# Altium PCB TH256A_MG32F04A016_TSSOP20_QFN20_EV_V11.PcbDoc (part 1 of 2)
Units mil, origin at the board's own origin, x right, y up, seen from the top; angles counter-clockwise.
Board outline 4094.49 x 2637.8 mil, 2 copper layers (Top Layer, Bottom Layer); 134 components, 99 nets, 551 pads, 259 vias.
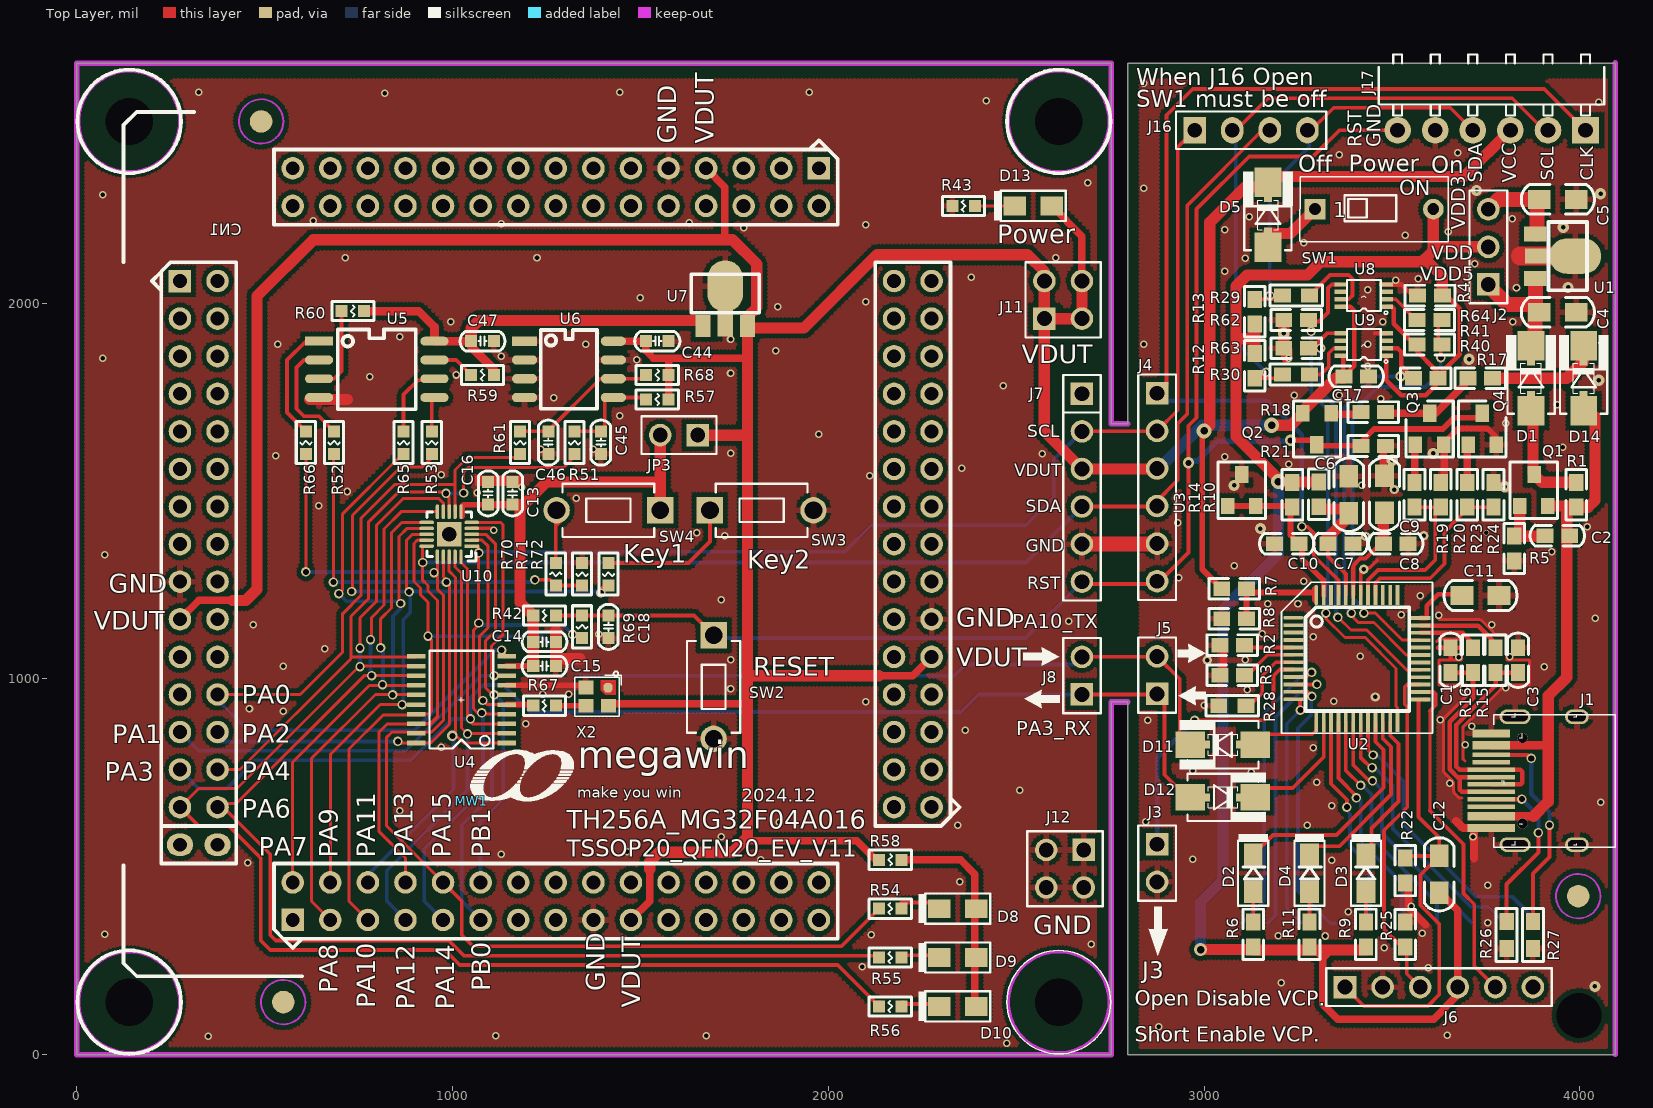
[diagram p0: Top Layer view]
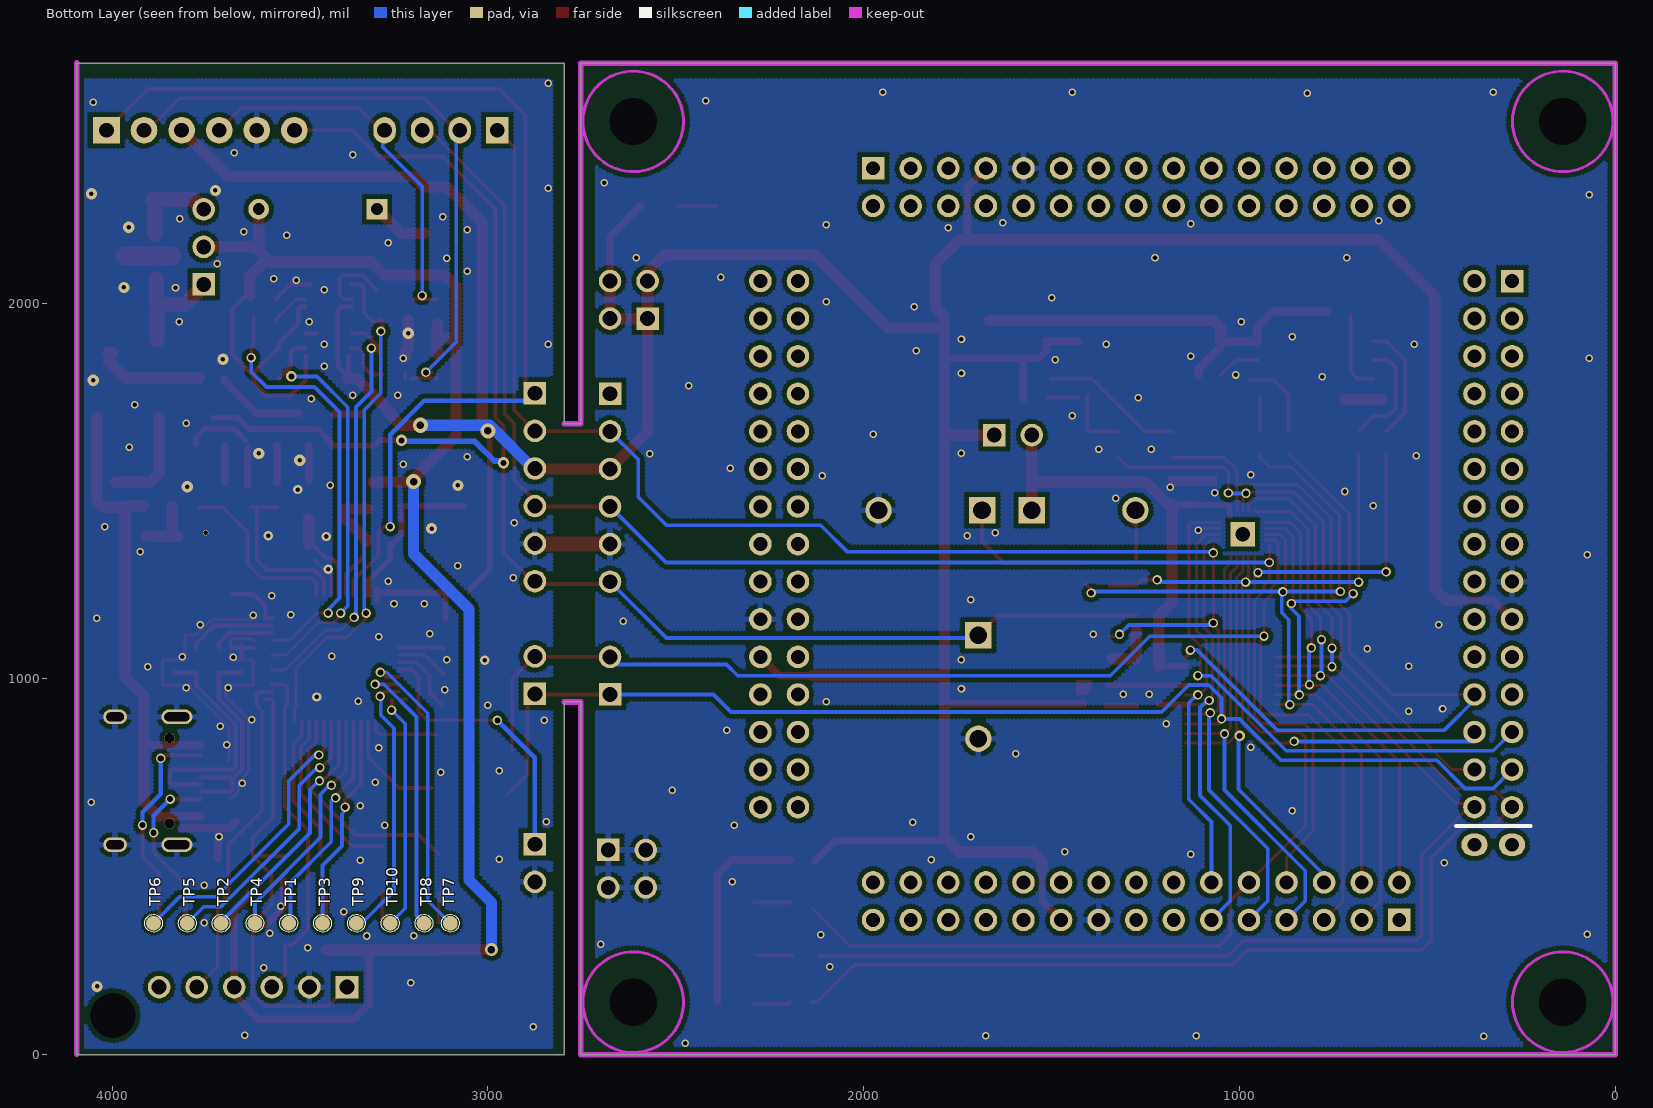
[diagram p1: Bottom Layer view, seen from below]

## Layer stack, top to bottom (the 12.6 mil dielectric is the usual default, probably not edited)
Top Layer: signal copper 1.4
Dielectric: dielectric 12.6, FR-4, Dk 4.8
Bottom Layer: signal copper 1.4

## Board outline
0,0 0,2637.8 2753.39,2637.8 2753.39,1678.74 2796.69,1678.74 2796.69,2637.8 4094.49,2637.8 4094.49,0 2796.69,0 2796.69,938.74 2753.39,938.74 2753.39,0

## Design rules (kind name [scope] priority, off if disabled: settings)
Clearance 12 [All] p1 off: gap=12
Clearance 7 [All] p2 off: gap=7
Clearance 6 [All] p3: gap=6
HoleSize 500-HoleSize [All] p1: absolutevalues=TRUE maxlimit=1500 minlimit=1 maxpercent=80.000 minpercent=20.000
PolygonConnect VIA [ISVIA] p1: connectstyle=Direct reliefconductorwidth=10 reliefentries=4 polygonreliefangle="90 Angle"
PolygonConnect "15 PolygonConnect" [All] p2: connectstyle=Relief reliefconductorwidth=15 reliefentries=4 polygonreliefangle="90 Angle"
RoomDefinition "3_MG32F04A016_QFN20 " [InComponentClass('3_MG32F04A016_QFN20 ')] p1: confinementstyle=ConfineIn formatcopy=TRUE lockcomponents=FALSE outline -70.96,-260.26 4008.04,-260.26 4008.04,2917.74 -70.96,2917.74
RoomDefinition 2_MG32F04A016_TSSOP20 [InComponentClass('2_MG32F04A016_TSSOP20')] p2: confinementstyle=ConfineIn formatcopy=TRUE lockcomponents=FALSE outline -190,-175 4240.04,-175 4240.04,2710 -190,2710
RoomDefinition 1_MLink_V14 [InComponentClass('1_MLink_V14')] p3: confinementstyle=ConfineIn formatcopy=TRUE lockcomponents=FALSE outline -110,-220 4180,-220 4180,2775 -110,2775
RoutingVias [All] p1: holewidth=16 width=25 viastyle="Through Hole" minholewidth=12 minwidth=25 maxholewidth=28 maxwidth=50
ShortCircuit [All] p1 off: allowed=FALSE
SilkscreenOverComponentPads [All] p1: minsilkscreentomaskgap=10
SolderMaskExpansion [All] p1: expansion=4
UnRoutedNet [All] p1 off:
Width [All] p1: maxlimit=100 minlimit=6 preferedwidth=8
24 further rules are at their usual default settings.

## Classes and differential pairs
component class 1_MLink_V14: C1 C2 C3 C4 C5 C6 C7 C8 C9 C10 C11 C12 C17 D1 D2 D3 D4 D5 D11 D12 D14 J1 J2 J3 J4 J5 J6 J16 J17 MW1 Q1 Q2 Q3 Q4 R1 R2 R3 R4 R5 R6 R7 R8 R9 R10 R11 R12 R13 R14 R15 R16 R17 R18 R19 R20 R21 R22 R23 R24 R25 R26 R27 R28 R29 R30 R40 R41 R62 R63 R64 SW1 TP1 TP2 TP3 TP4 TP5 TP6 TP7 TP8 TP9 TP10 U1 U2 U3 U8 U9
component class 2_MG32F04A016_TSSOP20: C14 C15 C18 C44 C45 C46 C47 CN1 D8 D9 D10 D13 J7 J8 J11 J12 JP3 R42 R43 R51 R52 R53 R54 R55 R56 R57 R58 R59 R60 R61 R65 R66 R67 R68 R69 R70 R71 R72 SW2 SW3 SW4 U4 U5 U6 U7 X2
component class "3_MG32F04A016_QFN20 ": C13 C16 U10

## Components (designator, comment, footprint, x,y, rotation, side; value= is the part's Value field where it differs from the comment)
C1 "15pF" 0603C 3655.59,1050 r270 top
C2 "0.1uF" 0603C 3940,1381.26 r0 top
C3 "15pF" 0603C 3835.59,1050 r270 top
C4 "4.7uF" 0805C 3941.38,1975.94 r0 top
C5 "4.7uF" 0805C 3941.38,2275.94 r0 top
C6 "4.7uF" 0805C 3385,1490 r90 top
C7 "0.1uF" 0603C 3363,1360 r0 top
C8 "0.1uF" 0603C 3510,1360 r0 top
C9 "4.7uF" 0805C 3480,1491.26 r90 top
C10 "0.1uF" 0603C 3220,1360 r0 top
C11 "4.7uF" 0805C 3735.59,1221.9 r0 top
C12 "4.7uF" 0805C 3625.59,480 r90 top
C13 "10uF" C-0603 1160.04,1493.74 r90 top
C14 "10uF" C-0603 1245.04,1098.74 r0 top
C15 "0.1uF" C-0603 1245.04,1034.34 r0 top
C16 "0.1uF" C-0603 1095.04,1493.74 r90 top
C17 "0.1uF" 0603C 3405,1805 r180 top
C18 "NC" C-0603 1415.04,1138.74 r90 top
C44 "0.1uF" C-0603 1545.04,1898.74 r0 top
C45 "47pF" C-0603 1395.04,1628.74 r270 top
C46 "47pF" C-0603 1255.04,1628.74 r270 top
C47 "0.1uF" C-0603 1080.04,1898.74 r0 top
CN1 "QFP122-CKT" QFP122-P2.54-CKT 1275.04,1358.74 r0 top locked
D1 "1N5817" DIODE_SMA_SOD323 3870,1800 r90 top
D2 "Yellow" 0805D 3130.59,483.26 r90 top
D3 "Green" 0805D 3430.59,483.26 r90 top
D4 "Red" 0805D 3280.59,483.26 r90 top
D5 "1N5817" DIODE_SMA_SOD323 3170,2235 r90 top
D8 "Red" 0805D 2344.25,388.74 r180 top
D9 "Yellow" 0805D 2344.25,258.74 r180 top
D10 "Green" 0805D 2344.25,128.74 r180 top
D11 "1N5817" DIODE_SMA_SOD323 3050.04,825 r180 top
D12 "1N5817" DIODE_SMA_SOD323 3050.04,685 r0 top
D13 "Yellow" 0805D 2545.04,2258.74 r180 top
D14 "1N5817" DIODE_SMA_SOD323 4010,1800 r90 top
J1 "CJ-USB3-C16P" USB_CF_16_SMD 3799.28,729.12 r90 top
J2 "2&3 (0 ohm)" PS3P254 3756.42,2049.69 r90 top
J3 "VCP Option" PS2P254 2875.04,560 r270 top
J4 "OnBoard ICP/SWD Connector" PS6P254 2875.04,1760 r270 top
J5 "NC" PS2P254 2875.04,960 r90 top
J6 "CON6" PS6P254 3375.04,180 r0 top
J7 "CON6" PS6P254 2675.04,1758.74 r270 top locked
J8 "NC" PS2P254 2675.04,958.74 r90 top
J11 "CONN SOCKET 2x2/SM" PS2X2P254 2575.04,1958.74 r0 top
J12 "CONN SOCKET 2x2/SM" PS2X2P254 2680,545 r180 top
J16 "When J16 Open, SW1 must be off." PS4P254 2975.04,2460 r0 top
J17 "Off Board ICP/SWD Connector" PS6P254_90 4015.04,2460 r180 top
JP3 "JUMPER" PS2P254 1652.83,1648.74 r180 top
MW1 "MW-A4" MEGAWIN_3.4_1 1051.14,674.84 r0 top
Q1 "IRLML6402" SOT23 3877.54,1501.97 r0 top
Q2 "2N3906" SOT23 3300.5,1665 r180 top
Q3 "3904" SOT23_132 3600.04,1665 r0 top
Q4 "3904" SOT23_132 3740.04,1665 r0 top
R1 "NC" 0603R#1 3990.04,1490 r270 top
R2 "NC" 0603R#1 3075.04,1090 r0 top
R3 "NC" 0603R#1 3075.04,1010 r0 top
R4 "3.3K" 0603R#1 3601,2020 r0 top
R5 "1M" 0603R#1 3825.04,1347 r270 top
R6 "1K" 0603R#1 3130.59,320.26 r270 top
R7 "30K" 0603R#1 3080,1240 r180 top
R8 "10K" 0603R#1 3080,1160 r0 top
R9 "1K" 0603R#1 3430.59,320.26 r270 top
R10 "10" 0603R#1 3305,1491.26 r90 top
R11 "1K" 0603R#1 3280.59,320.26 r270 top
R12 "1.5K" 0603R#1 3135,1833 r90 top
R13 "1.5K" 0603R#1 3135,1977 r270 top
R14 "1K" 0603R#1 3235,1490 r270 top
R15 "30" 0603R#1 3775.59,1050 r90 top
R16 "30" 0603R#1 3715.59,1050 r90 top
R17 "4.7K" 0603R#1 3735,1800 r0 top
R18 "1K" 0603R#1 3450.04,1710 r0 top
R19 "4.7K" 0603R#1 3560.04,1490 r270 top
R20 "10K" 0603R#1 3630.04,1490 r270 top
R21 "1M" 0603R#1 3450.04,1620 r180 top
R22 "47K" 0603R#1 3535.59,490 r270 top
R23 "4.7K" 0603R#1 3700.04,1490 r270 top
R24 "10K" 0603R#1 3770.04,1490 r270 top
R25 "47K" 0603R#1 3535.59,320 r270 top
R26 "5.1K" 0603R#2 3805.04,318.74 r270 top
R27 "5.1K" 0603R#2 3875.04,318.74 r90 top
R28 "0" 0603R#2 3075.04,928.74 r180 top
R29 "100" 0603R#2 3245,2020 r0 top
R30 "100" 0603R#2 3245,1810 r0 top
R40 "NC" 0603R#1 3590,1800 r180 top
R41 "1.5K" 0603R#1 3600,1890 r0 top
R42 "47K" R-0603 1245.04,1168.74 r0 top
R43 "1K" R-0603 2360.04,2258.74 r0 top
R51 "NC" R-0603 1325.04,1628.74 r90 top
R52 "NC" R-0603 685.04,1628.74 r90 top
R53 "NC" R-0603 945.04,1628.74 r90 top
R54 "470" R-0603 2165.04,388.74 r0 top
R55 "470" R-0603 2165.04,258.74 r0 top
R56 "470" R-0603 2165.04,128.74 r0 top
R57 "10K" R-0603 1545.04,1743.74 r180 top
R58 "0" R-0603 2165.04,518.74 r180 top
R59 "10K" R-0603 1080.04,1808.74 r0 top
R60 "10K" R-0603 735.04,1978.74 r180 top
R61 "NC" R-0603 1180.04,1628.74 r90 top
R62 "47k" 0603R#3 3245,1955 r0 top
R63 "47k" 0603R#3 3245,1880 r0 top
R64 "100" 0603R#3 3600,1955 r180 top
R65 "NC" R-0603 870.04,1628.74 r90 top
R66 "NC" R-0603 610.04,1628.74 r90 top
R67 "NC" R-0603 1245.04,928.74 r0 top
R68 "10K" R-0603 1545.04,1808.74 r180 top
R69 "NC" R-0603 1345.04,1138.74 r90 top
R70 "1K" R-0603 1275.04,1278.74 r270 top
R71 "1M" R-0603 1345.04,1278.74 r90 top
R72 "1K" R-0603 1415.04,1278.74 r90 top
SW1 "SW KEY-SPST" DIP2_SW 3295.04,2250 r0 top
SW2 "SW TACT-SPST" SW_T_2P 1695.04,978.74 r270 top
SW3 "Key2" SW_T_2P 1822.83,1448.74 r0 top
SW4 "Key1" SW_T_2P 1415.04,1448.74 r180 top
TP1 "T POINT A" PIN1_1H0 3530.04,350 r90 bottom
TP2 "T POINT A" PIN1_1H0 3710.04,350 r90 bottom
TP3 "T POINT A" PIN1_1H0 3440.04,350 r180 bottom
TP4 "T POINT A" PIN1_1H0 3620.04,350 r180 bottom
TP5 "T POINT A" PIN1_1H0 3800.04,350 r180 bottom
TP6 "T POINT A" PIN1_1H0 3890.04,350 r180 bottom
TP7 "T POINT A" PIN1_1H0 3100.04,350 r180 bottom
TP8 "T POINT A" PIN1_1H0 3170.04,350 r180 bottom
TP9 "T POINT A" PIN1_1H0 3350.04,350 r180 bottom
TP10 "T POINT A" PIN1_1H0 3260.04,350 r90 bottom
U1 "AIC1734-33(SOT-89)" SOT89 3881.38,2125 r270 top
U2 "MG84FG516_LQFP48" LQFP48_7X7_050 3406.51,1054.39 r270 top
U3 "TL431A" SOT23 3100,1501.97 r0 top
U4 "MG32F04A016_TSSOP20" TSSOP20_170P065 1144.04,829.54 r90 top locked
U5 "MX25L3206E" SO8_208P127 798.58,1823.74 r270 top
U6 "24C16-SOP8" SO8_150P127 1191.93,1898.74 r0 top
U7 "AIC1734-33(SOT-89)" SOT89 1725.98,1938.74 r0 top
U8 "SN74LVC2T45 (MSOP8_90P0.5)" MSOP8_90P0.5 3425,2020 r90 top
U9 "SN74LVC2T45 (MSOP8_90P0.5)" MSOP8_90P0.5 3425,1890 r90 top
U10 "MG32F04A016_QFN20  3x3P0.4mm" QFN20_3X3P040_1 991.41,1384.96 r90 top
X2 "OT20168MJBA4SL" OSC_2.0X1.6_SMD 1385.04,952.93 r180 top

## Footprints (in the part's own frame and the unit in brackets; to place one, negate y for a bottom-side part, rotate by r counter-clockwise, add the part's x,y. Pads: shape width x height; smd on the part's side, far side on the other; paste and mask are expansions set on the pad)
0603C [mil]
  rect 45x38 smd: 1(33,0) 2(-33,0)
  silkscreen extent -72,-28 72,28
0603R#1 [mil]
  rect 45x38 smd: 1(33,0) 2(-33,0)
  silkscreen extent -67,-28 67,28
0603R#2 [mil]
  rect 45x38 smd: 1(-36,0) 2(36,0)
  silkscreen extent -70,-28 70,28
0603R#3 [mil]
  rect 45x38 smd: 1(-33,0) 2(33,0)
  silkscreen extent -67,-28 67,28
0805C [mil]
  rect 60x50 smd: 1(-49.21,0) 2(49.21,0)
  silkscreen extent -97,-39 97,39
0805D [mil]
  rect 60x50 smd: 1(-49.21,0) 2(49.21,0)
  silkscreen extent -87,-40 104,40
C-0603 [mil]
  rect 32x32 smd: 1(-30,0) 2(30,0)
  silkscreen extent -60,-26 60,26
DIODE_SMA_SOD323 [mm]
  rect 2x1.8 smd: 1(-2.2,0) 2(2.2,0)
  rect 0.95x0.54 smd: 1(-1.35,0) 2(1.35,0)
  silkscreen extent -2.4,-1.68 2.92,1.68
DIP2_SW [mm]
  rect 1.4x1.4 hole 0.8: 1(0,0)
  round 1.4 hole 0.8: 2(8,0)
  silkscreen extent -1.02,-2.2 9.02,2.2
LQFP48_7X7_050 [mm]
  oval 0.254x1.35 smd: 1(-2.75,-4.292)
  rect 0.254x1.35 smd: 2(-2.25,-4.292) 3(-1.75,-4.292) 4(-1.25,-4.292) 5(-0.75,-4.292) 6(-0.25,-4.292) 7(0.25,-4.292) 8(0.75,-4.292) 9(1.25,-4.292) 10(1.75,-4.292) 11(2.25,-4.292) 12(2.75,-4.292) 25(2.763,4.292) 26(2.263,4.292) 27(1.763,4.292) 28(1.263,4.292) 29(0.763,4.292) 30(0.263,4.292) 31(-0.237,4.292) 32(-0.737,4.292) 33(-1.237,4.292) 34(-1.737,4.292) 35(-2.237,4.292) 36(-2.737,4.292)
  rect 1.35x0.254 smd: 13(4.286,-2.744) 14(4.286,-2.244) 15(4.286,-1.744) 16(4.286,-1.244) 17(4.286,-0.744) 18(4.286,-0.244) 19(4.286,0.256) 20(4.286,0.756) 21(4.286,1.256) 22(4.286,1.756) 23(4.286,2.256) 24(4.286,2.756) 37(-4.286,2.756) 38(-4.286,2.256) 39(-4.286,1.756) 40(-4.286,1.256) 41(-4.286,0.756) 42(-4.286,0.256) 43(-4.286,-0.244) 44(-4.286,-0.744) 45(-4.286,-1.244) 46(-4.286,-1.744) 47(-4.286,-2.244)
  oval 1.35x0.254 smd: 48(-4.286,-2.744)
  silkscreen extent -5.15,-5.09 5.05,5.11
MEGAWIN_3.4_1 [mil]
  silkscreen extent -2,0 272,135
MSOP8_90P0.5 [mm]
  rect 0.3x0.85 smd: 1(-0.75,-1.55) 2(-0.25,-1.55) 3(0.25,-1.55) 4(0.75,-1.55) 5(0.75,1.55) 6(0.25,1.55) 7(-0.25,1.55) 8(-0.75,1.55)
  silkscreen extent -1.26,-1.61 1.05,1.14
OSC_2.0X1.6_SMD [mil]
  oct 25x25 smd: 1(-29,-24)
  rect 40x37 smd: 2(30,-24.19) 3(30,24.19) 4(-30,24.19)
  Top Layer region: -50,-43 -50,-5 -21,-5 -9,-17 -9,-43
  silkscreen extent -64,-67 60,52
PIN1_1H0 [mm]
  round 1 smd: 1(0,0)
  silkscreen extent -0.6,-0.6 0.6,0.6
PS2P254 [mil]
  rect 60x60 hole 39.37: 1(0,0)
  round 60 hole 39.37: 2(100,0)
  silkscreen extent -50,-50 150,50
PS2X2P254 [mil]
  rect 60x60 hole 39.37: 1(0,0)
  round 60 hole 39.37: 2(0,100) 3(100,0) 4(100,100)
  silkscreen extent -50,-50 150,150
PS3P254 [mil]
  rect 60x60 hole 39.37: 1(0,0)
  round 60 hole 39.37: 2(100,0) 3(200,0)
  silkscreen extent -50,-50 250,50
PS4P254 [mil]
  rect 60x70 hole 39.37: 1(0,0)
  oval 60x70 hole 39.37: 2(100,0) 3(200,0) 4(300,0)
  silkscreen extent -50,-50 350,50
PS6P254 [mil]
  rect 60x60 hole 39.37: 1(0,0)
  round 60 hole 39.37: 2(100,0) 3(200,0) 4(300,0) 5(400,0) 6(500,0)
  silkscreen extent -50,-50 550,50
PS6P254_90 [mm]
  rect 1.8x1.8 hole 1: 1(0,0)
  round 1.8 hole 1: 2(2.54,0) 3(5.08,0) 4(7.62,0) 5(10.16,0) 6(12.7,0)
  silkscreen extent -1.27,-5.11 13.97,-1
QFN20_3X3P040_1 [mil]
  rect 64.96x64.96 hole 39.37: 0(0,0)
  rect 9x39.37 smd: 1(-31.5,-60)
  oval 9x39.37 smd: 2(-15.75,-60) 3(0,-60) 4(15.75,-60) 5(31.5,-60) 11(31.5,60) 12(15.75,60) 13(0,60) 14(-15.75,60) 15(-31.5,60)
  oval 39.37x9 smd: 6(60,-31.5) 7(60,-15.75) 8(60,0) 9(60,15.75) 10(60,31.5) 16(-60,31.5) 17(-60,15.75) 18(-60,0) 19(-60,-15.75) 20(-60,-31.5)
  silkscreen extent -71,-71 59,59
QFP122-P2.54-CKT [mil]
  rect 60x60 hole 37: 1(-700,-1000) 61(700,1000) 91(-1000,700)
  round 60 hole 37: 2(-700,-900) 3(-600,-1000) 4(-600,-900) 5(-500,-1000) 6(-500,-900) 7(-400,-1000) 8(-400,-900) 9(-300,-1000) 10(-300,-900) 11(-200,-1000) 12(-200,-900) 13(-100,-1000) 14(-100,-900) 15(0,-1000) 16(0,-900) 17(100,-1000) 18(100,-900) 19(200,-1000) 20(200,-900) 21(300,-1000) 22(300,-900) 23(400,-1000) 24(400,-900) 25(500,-1000) 26(500,-900) 27(600,-1000) 28(600,-900) 29(700,-1000) 30(700,-900) 31(1000,-700) 32(900,-700) 33(1000,-600) 34(900,-600) 35(1000,-500) 36(900,-500) 37(1000,-400) 38(900,-400) 39(1000,-300) 40(900,-300) 41(1000,-200) 42(900,-200) 43(1000,-100) 44(900,-100) 45(1000,0) 46(900,0) 47(1000,100) 48(900,100) 49(1000,200) 50(900,200) 51(1000,300) 52(900,300) 53(1000,400) 54(900,400) 55(1000,500) 56(900,500) 57(1000,600) 58(900,600) 59(1000,700) 60(900,700) 62(700,900) 63(600,1000) 64(600,900) 65(500,1000) 66(500,900) 67(400,1000) 68(400,900) 69(300,1000) 70(300,900) 71(200,1000) 72(200,900) 73(100,1000) 74(100,900) 75(0,1000) 76(0,900) 77(-100,1000) 78(-100,900) 79(-200,1000) 80(-200,900) 81(-300,1000) 82(-300,900) 83(-400,1000) 84(-400,900) 85(-500,1000) 86(-500,900) 87(-600,1000) 88(-600,900) 89(-700,1000) 90(-700,900) 92(-900,700) 93(-1000,600) 94(-900,600) 95(-1000,500) 96(-900,500) 97(-1000,400) 98(-900,400) 99(-1000,300) 100(-900,300) 101(-1000,200) 102(-900,200) 103(-1000,100) 104(-900,100) 105(-1000,0) 106(-900,0) 107(-1000,-100) 108(-900,-100) 109(-1000,-200) 110(-900,-200) 111(-1000,-300) 112(-900,-300) 113(-1000,-400) 114(-900,-400) 115(-1000,-500) 116(-900,-500) 117(-1000,-600) 118(-900,-600) 119(-1000,-700) 120(-900,-700)
  oval 70x60 hole 37: 121(-1000,-800) 122(-900,-800)
  silkscreen extent -1150,-1150 1075,1150
R-0603 [mil]
  rect 32x32 smd: 1(-30,0) 2(30,0)
  silkscreen extent -56,-26 56,26
SO8_150P127 [mil]
  rect 67x25 smd: 1(0,0)
  oval 67x25 smd: 2(0,-50) 3(0,-100) 4(0,-150) 5(236.22,-150) 6(236.22,-100) 7(236.22,-50) 8(236.22,0)
  silkscreen extent 43,-180 193,30
SO8_208P127 [mm]
  rect 0.6x1.9 smd: 1(-1.905,-3.9)
  oval 0.6x1.9 smd: 2(-0.635,-3.9) 3(0.635,-3.9) 4(1.905,-3.9) 5(1.905,3.9) 6(0.635,3.9) 7(-0.635,3.9) 8(-1.905,3.9)
  silkscreen extent -2.69,-2.63 2.69,2.63
SOT23 [mil]
  rect 36x43.31 smd: 1(-37.5,-41.97) 2(37.5,-41.97)
  rect 36x46.06 smd: 3(0.5,41.97)
  silkscreen extent -63,-74 63,75
SOT23_132 [mil]
  rect 36x43.31 smd: 1(-37.5,-41.97) 3(37.5,-41.97)
  rect 36x46.06 smd: 2(0.5,41.97)
  silkscreen extent -63,-74 63,75
SOT89 [mm]
  rect 1.016x1.5 smd: 1(-1.5,0) 3(1.5,0)
  oval 2.4x3.5 smd: 2(0,2.7)
  rect 1.016x2.6 smd: 2(0,0.6)
  silkscreen extent -2.3,0.9 2.3,3.5
SW_T_2P [mil]
  rect 70x70 hole 47.24: 1(-137.79,0)
  round 70 hole 47.24: 2(137.8,0)
  silkscreen extent -122,-71 122,71
TSSOP20_170P065 [mil]
  rect 12x49 smd: 1(0,0) 2(25.6,0) 3(51.2,0) 4(76.8,0) 5(102.4,0) 6(128,0) 7(153.6,0) 8(179.2,0) 9(204.8,0) 10(230.4,0) 11(230.4,240.16) 12(204.8,240.16) 13(179.2,240.16) 14(153.6,240.16) 15(128,240.16) 16(102.4,240.16) 17(76.8,240.16) 18(51.2,240.16) 19(25.6,240.16) 20(0,240.16)
  silkscreen extent -15,35 245,205
USB_CF_16_SMD [mm]
  rect 0.55x3.2 smd: A1(-3.2,0.9) A4(-2.4,0.9)
  rect 0.3x3.2 smd: A5(-1.25,0.9) A6(-0.25,0.9) A7(0.25,0.9) B6(0.75,0.9) B7(-0.75,0.9) B8(-1.75,0.9)
  rect 0.3x2.54 smd: A8(1.25,0.9) B5(1.75,0.9)
  rect 0.55x2.54 smd: A9(2.4,0.9) A12(3.2,0.9)
  oval 1x2.1 hole 0.6 slot 1.7 at 90 deg: M1(-4.32,-0.718) M2(4.32,-0.718)
  oval 1x1.6 hole 0.6 slot 1.2 at 90 deg: M3(4.32,-4.898) M4(-4.32,-4.898)
  round 0.7 hole 0.7 unplated: M5(-2.89,-1.218) M6(2.89,-1.218)
  silkscreen extent -4.48,-7.5 4.55,0.74

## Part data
C1 C3 C7 C12 C13 C14 C15 C16 C18: library part "CAP NP_Dup1"
C2 C8 C10 C17: library part "CAP NP"
C4 C5: library part "C NP"
C6 C9 C11: library part CAP
C44 C45 C46 C47: library part CAP-NP
D1 D5 D11 D12 D14: library part "DIODE SCHOTTKY"
D2 D3 D4: library part Led0_0
D8 D9 D10 D13: library part LED
J1: "TPYE-C-9"
J2: library part CON3
J3 J5 J8: library part CON2
J4 J17: library part CON6
J7: library part CON6_Dup1
J16: library part CON4
MW1: library part MW_A4_2
Q1: library part "MOSFET P GSD"
Q2: library part 2N3906_0
Q3 Q4: library part "NPN BCE"
R1 R2 R3 R4 R28 R43 R54 R55 R56 R58: library part R_Dup4
R5 R6 R7 R8 R9 R11 R12 R13 R17 R18 R19 R22 R23 R25 R26 R27 R29 R30: library part R_Dup2
R10 R14 R15 R16: library part R_Dup5
R20 R21 R24: library part R_Dup1
R40 R41 R42 R62 R63 R70 R71 R72: library part R_Dup3
R51 R52 R53 R57 R59 R60 R61 R64 R65 R66 R67 R68 R69: library part R
SW3 SW4: library part "SW TACT-SPST"
U1 U7: library part AIC1722-33
U3: library part TL431/CYL
U4: library part MG32F003_TSSOP20
U6: library part ICM-24CXX
U8 U9: library part SN74LVC2T45
U10: library part MG32F003_QFN20
X2: library part OSC8_0

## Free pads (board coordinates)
  round 120 hole 125.98 unplated: 0(140,140) 0(140,2483.43) 0(2613.39,140) 0(2613.39,2483.43)
  round 60 smd mask+39.37: 0(491,2483.43) 0(550,140) 0(3995.59,421.9)
  round 100 hole 120 unplated: 0(3997.8,104.65)

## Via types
v1: diameter 20, hole 12, Top Layer to Bottom Layer, tented both sides, 173 vias
v2: diameter 25, hole 16, Top Layer to Bottom Layer, tented both sides, 58 vias
v3: diameter 30, hole 12, Top Layer to Bottom Layer, tented both sides, 13 vias
v4: diameter 25, hole 12, Top Layer to Bottom Layer, tented both sides, 6 vias
v5: diameter 40, hole 20, Top Layer to Bottom Layer, tented both sides, 3 vias
v6: diameter 28, hole 16, Top Layer to Bottom Layer, tented both sides, 2 vias
v7: diameter 30, hole 16, Top Layer to Bottom Layer, tented both sides, 2 vias
v8: diameter 35, hole 20, Top Layer to Bottom Layer, tented both sides, 1 vias
v9: diameter 15, hole 12, Top Layer to Bottom Layer, tented both sides, 1 vias

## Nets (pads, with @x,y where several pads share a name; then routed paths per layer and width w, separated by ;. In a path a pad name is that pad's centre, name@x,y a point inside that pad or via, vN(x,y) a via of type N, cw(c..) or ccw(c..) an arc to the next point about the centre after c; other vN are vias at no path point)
2.495V: C10.1 R14.1 U2.47 U3.1 U3.2 | length 442.3
  Top Layer w15: U3.1@3062.5,1460 U3.2@3137.5,1460 R14.1@3235,1460 ; R14.1@3230,1452 3230,1383 C10.1@3253,1360 3260.59,1360 3260.59,1319.45 3318.18,1261.86 U2.47@3318.18,1223.13
516P24: TP7.1 U2.9 | length 807.9
  Top Layer w10: U2.9@3237.52,1005.18 3271.48,1005.18 v2@3285.04,1018.74
  Bottom Layer w10: TP7.1@3100.04,350 3160.04,410 3160.04,908.74 3269.04,1017.74 v2(3286.04,1017.74)
516P25: TP8.1 U2.10 | length 765.6
  Top Layer w10: U2.10@3237.52,985.49 v2@3300.04,985.49
  Bottom Layer w10: TP8.1@3170.04,350 3190.04,370 3190.04,898.74 3277.04,985.74 v2(3300.04,985.74)
516P26: TP9.1 U2.11 | length 719.6
  Top Layer w10: U2.11@3237.52,965.81 3275.04,965.81 v2@3285.04,955.81
  Bottom Layer w10: v2@3285.04,953.74 3285.04,903.74 3250.04,868.74 3250.04,435.95 3335.99,350 TP9.1@3350.04,350
  other v2: 3287.04,953.74
516P27: TP10.1 U2.12 | length 651.8
  Top Layer w10: U2.12@3217.15,946.12 U2.12@3237.52,946.12 ; v2@3255.04,911.51 3255.04,916.74 U2.12@3255.04,944.74
  Bottom Layer w10: v2(3256.04,916.74) 3220.04,880.74 3220.04,390 TP10.1@3260.04,350
516P32: TP3.1 U2.15 | length 550.9
  Top Layer w10: U2.15@3337.86,885.65 3337.86,720.92 3380.04,678.74 v2@3380.04,668.74
  Bottom Layer w10: 3385.04,643.74 3388.62,640.16 3388.62,555.16 3440.04,503.74 TP3.1@3440.04,350
  other v2: 3380.04,658.74
516P33: TP1.1 U2.16 | length 664
  Top Layer w10: U2.16@3357.55,885.65 3357.55,736.23 v2@3407.54,686.24 ; v2@3409.54,688.24 v2@3412.04,685.74
  Bottom Layer w10: v2@3405.04,688.74 3407.54,686.24 3416.9,676.88 3416.9,566.88 ; 3416.9,618.74 3416.9,566.88 ; TP1.1@3525.04,350 3525.04,458.74 3416.9,566.88
  other v2: 3405.04,683.74
516P34: TP4.1 U2.17 | length 635.3
  Top Layer w10: U2.17@3377.23,885.65 3377.23,756.55 v2(3416.72,717.06)
  Bottom Layer w10: v2@3420.64,717.8 3445.19,693.26 3445.19,578.59 3620.04,403.74 TP4.1@3620.04,350
516P35: TP2.1 U2.18 | length 668.2
  Top Layer w10: U2.18@3396.92,885.65 3396.92,770.86 3443.54,724.24 v2@3445.04,722.74
  Bottom Layer w10: v2@3450.04,728.74 3473.47,705.31 3473.47,590.31 TP2.1@3711.91,351.87
  other v2: 3448.04,728.74
516P36: TP5.1 U2.19 | length 736.6
  Top Layer w10: U2.19@3416.6,885.65 3416.6,791.18 v2@3445.54,762.24
  Bottom Layer w10: v2(3447.04,763.74) 3455.04,763.74 3501.76,717.02 3501.76,602.02 3710.04,393.74 3756.3,393.74 TP5.1@3800.04,350 TP5.1@3790.59,350
516P37: TP6.1 U2.20 | length 795.9
  Top Layer w10: U2.20@3436.29,885.65 3436.29,811.49 v2(3450.04,797.74)
  Bottom Layer w10: v2(3450.04,797.74) 3461.04,797.74 3530.04,728.74 3530.04,613.74 3723.04,420.74 3819.3,420.74 TP6.1@3890.04,350 TP6.1@3880.59,350
CHIP_VDD: C13.1 C14.1 C15.1 C16.1 JP3.2 R42.1 SW4.1 U4.9 U10.6 | length 1261.5
  Top Layer w15: U10.6@1025.94,1433.64 1025.94,1441.64 1026.08,1441.78 1026.08,1444.96 1026.08,1459.78 1030.04,1463.74 C16.1@1095.04,1463.74 1115.04,1463.74 ; U4.9@1144.04,1034.34 C15.1@1215.04,1034.34
  Top Layer w20: 1115.04,1463.74 C13.1@1160.04,1463.74
  Top Layer w30: 1180.04,1463.74 1180.04,1203.74 R42.1@1215.04,1168.74 C14.1@1215.04,1098.74 C15.1@1215.04,1034.34 ; 1190.04,1463.74 1250.04,1523.74 1550.04,1523.74 ; SW4.1@1552.83,1448.74 JP3.2@1552.83,1648.74
D+: C3.1 J1.A6 J1.B6 R15.2 | length 648.6
  Top Layer w12: J1.A6@3763.84,719.27 3842.37,719.27 3847.09,724 3847.09,753 3841.45,758.64 J1.B6@3763.84,758.64 3679.95,758.64 3671.59,767 3671.59,878.54 3775.59,982.54 R15.2@3775.59,1017 C3.1@3835.59,1017
D-: C1.1 J1.A7 J1.B7 R16.2 | length 590.1
  Top Layer w12: C1.1@3655.59,1017 R16.2@3715.59,1017 3715.59,948 3653.59,886 3653.59,759.54 3679.75,733.39 ; 3675.59,738.96 3685.99,738.96 ; 3680.59,734.23 3680.59,705.23 3686.23,699.59 J1.B7@3763.84,699.59 ; 3680.94,733.9 3685.99,738.96 ; J1.A7@3763.84,738.96 3685.99,738.96
DET_VDUT: R7.2 R8.1 U2.48 | length 292.1
  Top Layer w15: R8.1@3113,1160 R7.2@3113,1240 3123,1230 3290.98,1230 ; U2.48@3295.04,1210 3295.04,1223.13 U2.48@3295.04,1240
DUT_CLK: J4.1 J17.1 U2.45 | length 2846.5
  Top Layer w10: J4.1@2875.04,1760 2900.04,1785 2900.04,2500.04 2970,2570 3905.04,2570 J17.1@4015.04,2460 ; v2(3260,1405) 3275,1405 3292,1388 3292,1327.92 3357.55,1262.37 U2.45@3357.55,1223.13
  Bottom Layer w12: J4.1@2875.04,1760 2880.04,1760 2900.04,1740 3170,1740 3260,1650 v2(3260,1405)
DUT_RST: C18.2 J4.6 J7.6 J17.6 Q2.3 Q4.2 R21.1 R42.2 R69.2 SW2.1 | length 4299.7
  Top Layer w10: R42.2@1275.04,1168.74 R69.2@1345.04,1168.74 C18.2@1415.04,1168.74 ; 1537.24,1168.74 C18.2@1415.04,1168.74 ; SW2.1@1695.04,1116.54 1642.83,1168.74 C18.2@1415.04,1168.74 ; J7.6@2676.04,1252.74 2875.04,1252.74 2878.67,1256.37 2958.79,1336.49 v7(2958.79,1575) 2958.79,1673.79 2980.04,1695.04 2980.04,2250.04 3120,2390 3290,2390 3360,2460 J17.6@3515.04,2460
  Top Layer w15: v7(3230,1635) 3288.03,1635 Q2.3@3300,1623.03 ; Q2.3@3308.03,1620 R21.1@3417.04,1620 3417.04,1629.56 3452.48,1665 3635,1665 3665,1695 Q4.2@3730.63,1695
  Bottom Layer w10: SW2.1@1695.04,1108.74 2525.04,1108.74 J7.6@2675.04,1258.74
  Bottom Layer w15: v7(2958.79,1575) 2958.79,1580 2983,1580 3035,1632 v7@3230,1632
DUT_SCL: J16.2 J17.2 R12.2 R30.1 | length 1704.6
  Top Layer w10: J16.2@3075.04,2460 3085,2460 3170,2545 3820,2545 J17.2@3905,2460 ; R12.2@3135,1800 3165,1800 R30.1@3203.31,1800 ; R12.2@3150,1816 3150.5,1815.5 3157.5,1808.5 3165,1801 ; R30.1@3205,1798.31 R30.1@3205,1800 ; R30.1@3220,1800 3220,1810 R30.1@3220,1812.69 ; J17.2@3890,2460 J17.2@3905,2460 ; J17.2@3910.02,2465.02 J17.2@3915.04,2460 J17.2@3905,2460
  Bottom Layer w10: J16.2@3084.3,2450.74 3084.3,1896.7 v2(3165,1816)
DUT_SDA: J16.4 J17.4 R13.2 R29.1 | length 1034.3
  Top Layer w10: R13.2@3135,2010 3175,2010 R29.1@3199,2010 ; J16.4@3280.02,2455.02 3345,2520 3655.04,2520 J17.4@3715.04,2460
  Bottom Layer w10: v2@3175,2015 v2(3175,2020) 3175,2310 3280.02,2415.02 J16.4@3280.02,2455.02
FAIL: D4.2 U2.22 | length 476
  Top Layer w10: D4.2@3280.59,555 3360.14,555 3497.35,692.22 3497.35,819.59 3475.66,841.28 U2.22@3475.66,885.65
GND_POWER: C1.2 C3.2 C4.2 C5.2 C6.2 C7.1 C8.1 C9.2 C10.2 C11.2 C13.2 C14.2 C15.2 C16.2 C17.2 C18.1 C44.2 C45.2 C46.2 C47.2 CN1.17 CN1.41 CN1.69 CN1.107 J1.A1 J1.A12 J1.M1 J1.M2 J1.M3 J1.M4 J3.2 J4.5 J6.2 J7.5 J12.1 J12.2 J12.3 J12.4 J17.5 Q3.3 Q4.3 R2.2 R3.2 R4.2 R5.1 R8.2 R20.2 R21.2 R22.1 R24.2 R25.2 R26.2 R27.1 R28.2 R43.1 R62.1 R63.1 R71.2 SW2.2 SW3.2 U1.2 U2.42 U3.3 U4.7 U5.4 U6.1 U6.2 U6.3 U6.4 U6.7 U7.2 U8.4 U9.4 U10.4 X2.2 | length 3602
  Top Layer w8: 3619.08,1099.79 3625.08,1105.79 3655.59,1105.79 3680.76,1105.79 3685.59,1100.96 3685.59,1058 3685.59,1050.5 3677.59,1050.5 3625.59,1050.5 3625.59,983.5 3690.59,983.5 3698.59,983.5 3698.59,977 3698.59,955.04 3641.57,898.02 ; v1@3619.59,1164 3625.12,1158.47 3729.12,1158.47 ; 3641.57,747.52 cw(c3653.59,759.54) 3636.59,759.54 ; 3641.59,898 ccw(c3653.61,885.98) 3636.61,885.98 3636.59,759.54 ; 3674.21,687.57 ccw(c3686.23,699.59) 3686.23,682.59 cw(c3686.23,699.59) 3674.19,687.59 3668.59,693.19 ; 3694.59,781.64 3688.59,787.64 3688.59,825 3688.59,871.5 3787.59,970.5 ccw(c3775.59,982.54) 3792.59,982.54 cw(c3775.59,982.54) 3787.61,970.52 ; 3792.59,983.5 3802.59,983.5 3865.59,983.5 3865.59,1050.5 3813.59,1050.5 3805.59,1050.5 3805.59,1059 3805.59,1116.5 3778.13,1116.5 3758.11,1136.52 3741.16,1153.47 ; 3636.59,759.54 ccw(c3653.59,759.54) 3641.59,747.5 3660.34,728.75 3663.59,725.5 3663.59,722 3663.59,705.23 ; 3663.59,705.23 ccw(c3680.59,705.23) 3668.57,693.21 ; 3663.59,705.23 ccw(c3680.59,705.23) 3668.59,693.19 ; 3729.12,1158.47 cw(c3729.12,1141.47) 3741.16,1153.47 ; 3729.12,1158.47 cw(c3729.12,1141.47) 3741.14,1153.49
  Top Layer w10: U10.4@1051.41,1400.71 1105.07,1400.71 v1(1110.04,1395.74) ; U2.42@3416.6,1223.13 3416.6,1283.6 v4(3425,1292) 3429,1296 3441,1296 3461,1316
  Top Layer w12: 3455,1919.53 U9.4@3486.02,1919.53 ; U8.4@3471.02,2049.53 U8.4@3486.02,2049.53 3510,2049.53 3525.47,2049.53 3561.5,2013.5 R4.2@3565,2010 ; 3623.59,1083 C1.2@3655.59,1083 C1.2@3656.59,1083 ; 3656.59,1054 C1.2@3656.59,1083 ; C1.2@3656.59,1091 C1.2@3656.59,1083 ; 3683.59,1083 C1.2@3656.59,1083
  Top Layer w15: 1215.04,983.14 U4.7@1144.04,983.14 X2.2@1350.04,983.14 ; Q3.3@3645.29,1635.29 3676.24,1666.24 3753.7,1666.24 3777.54,1642.4 Q4.3@3777.54,1623.03
  Top Layer w20: R3.2@3051.04,1010 3051.04,1090 R2.2@3051.04,1090.09 ; C9.2@3477.04,1528 3477.04,1540.47 3477.04,1582 R21.2@3477.04,1620 ; R22.1@3543.59,461 3543.59,457 3543.59,395.74 3543.59,391.89 3545.39,390.09 3559.03,376.44 3590.08,345.4 ; R20.2@3639.04,1515 3639.04,1523 Q3.3@3639.04,1612.53
  Top Layer w22: 3670.59,621.9 3689.38,603.12 J1.A1@3763.84,603.12 J1.A1@3815.59,603.12 ; 3718.47,522.79 3718.47,580 J1.A1@3718.47,597.25
  Top Layer w30: U5.4@619.94,1743.74 645.04,1743.74 719.94,1743.74 ; 1275.04,1053.74 1339.44,1053.74 ; 1275.04,1062.34 C14.2@1275.04,1098.74 1275.04,1126.74 ; R63.1@3212,1880 v3(3212,1920) R62.1@3212,1955 ; v1@3220,1855 R63.1@3220,1875
  Top Layer w40: J7.5@2675.04,1358.74 J4.5@2875.04,1358.74
  Top Layer w50: 3841.82,2125 U1.2@3905,2125 U1.2@3966.38,2125
  other v1: 2475.04,30.64 349.94,48.74 1115.04,50.64 1675.04,50.64 3647.59,51.9 2879.94,75 3205.59,191.9 3596.59,231.9 2089.94,233.74 3479.94,285 2699.94,293.74 3322.59,316 3197.59,317 2115.04,318.74 75.04,320.64 3579.94,323.74 3755,350.64 3384.04,380.64 3551.04,395.74 3755,450.64 2350.04,460.64 455.04,510.64 3339.94,518 1819.94,518.74 2969.94,520 1129.94,533.74 1465.04,540.64 3715.59,580 1715.04,580.64 2345.04,610.64 3275.04,610.64 1869.94,618.74 2845.04,620 859.94,648.74 3339.94,662.74 4055.59,671.9 2509.94,703.74 3653.59,722 3299.94,725.74 3125.04,751.9 2969.94,756 1595.04,800.64 3289.94,816.74 969.94,818.74 3695.59,825 2365.04,863.74 3712.59,874 1195.04,880.64 2850,890.64 3628.59,891.9 549.94,913.74 460.04,920.64 2999.94,930 2099.94,938.74 3345,940.64 1240.04,958.74 1310.04,958.74 3115,970.64 1739.94,973.74 3802.59,976 3690.59,977 3905.59,1031.9 549.94,1033.74 1740.04,1050.64 3110,1050.64 3677.59,1058 3813.59,1059 3415,1060.64 660.04,1080.64 3290.04,1111.9 1389.94,1118.74 3155,1120.64 469.94,1143.74 3765.59,1144 2639.94,1153.74 4040.59,1161.9 3624.59,1170 3525,1171 3169.94,1200 3249.94,1200 1715.04,1210.64 3575.04,1221.9 3265.04,1260 2932,1269.26 3080,1300.64 75.04,1330.64 3924.59,1339 1725.04,1380.64 1649.94,1388.74 4019.94,1405 2929.94,1415 644.04,1460.74 1330.04,1480.64 1066.04,1495.74 719.94,1498.74 1185.04,1510.64 3419.94,1515 2110.04,1540.64 969.94,1543.74 2355.04,1560.64 3225,1570.64 3055,1590.64 529.94,1593.74 2569.94,1598.74 1740.04,1600.64 1235.04,1610.64 1375.04,1610.64 3955,1616.26 1975.04,1650.64 3803.03,1680 1445.04,1700.64 3939.94,1730 3470,1745 1269.94,1748.74 3239.94,1755 3360,1755 2465.04,1780.64 779.94,1803.74 1009.94,1808.74 1739.94,1813.74 3435,1832.56 1489.94,1848.74 3225,1853 69.94,1853.74 1129.94,1858.74 1859.94,1873.74 2839.94,1890 535.04,1890.64 1355.04,1890.64 3435,1890.64 1739.94,1903.74 860.04,1910.64 995.04,1950.64 3475,1950.64 3821.38,1950.94 1865.04,1990.64 2099.94,2003.74 1499.94,2013.74 3434.94,2035 3831.32,2040.94 3510,2060.64 3569.94,2065 2379.94,2068.74 3055,2085 3719.94,2105 3109.94,2120 715.04,2120.64 1225.04,2120.64 2605.04,2120.64 3265,2160.64 3535,2180.64 3649.94,2189.59 3055,2195 1775.04,2200.64 2099.94,2208.74 1130.04,2210.64 1629.94,2213.74 629.94,2218.74 3819.94,2225 3119.94,2230 69.94,2288.74 2839.94,2305 2690.04,2320.64 3359.94,2395 3675,2400.64 4049.94,2535 2419.94,2538.74 819.94,2558.74 325.04,2560.64 1445.04,2560.64 1950.04,2560.64 2839.94,2585
  other v3: 4040.04,181.9 3150,1400 3800,1511.26 3079.94,1515 3500.59,1582 3609.94,1600 4049.94,1795 3705,1850.64 3968.42,2041.59 3955.97,2201.69 4055,2290.64 3725,2299.69
  other v4: 3455.59,952 3008.11,1050 3430.59,1379 3585,1381.26 3506,1504
  other v9: 3750.59,1389
ICP/SWD_SCL: R40.1 U2.31 U9.2 | length 1093
  Top Layer w8: v2@3392,1168 3410,1150 3452,1150 3538.27,1063.73 U2.31@3575.5,1063.73
  Top Layer w12: U9.2@3486.02,1880.16 3514.84,1880.16 3525,1870 3525,1832 R40.1@3557,1800
  Bottom Layer w10: v2(3392,1175) 3373,1194 3373,1723 3455,1805 v6(3523.07,1805)
ICP/SWD_SDA: R41.1 R64.1 U2.33 | length 1167.1
  Top Layer w8: v2(3425,1175) 3456,1175 3527.9,1103.1 U2.33@3575.5,1103.1
  Top Layer w10: R64.1@3623,1965 3623,1955 3623,1890 3628,1885 3630,1883 v2(3630,1855)
  Bottom Layer w10: 3395,1505 3395,1495 ; v2@3423,1175 3423,1187 3395,1215 3395,1495 ; v2(3630,1855) 3630,1817 3589.47,1776.47 3461.47,1776.47 3395,1710 3395,1495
